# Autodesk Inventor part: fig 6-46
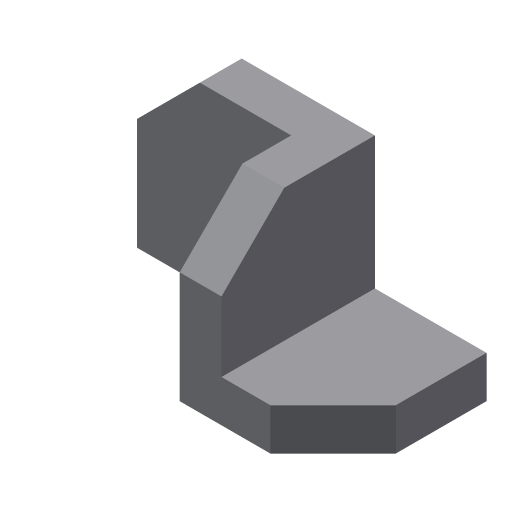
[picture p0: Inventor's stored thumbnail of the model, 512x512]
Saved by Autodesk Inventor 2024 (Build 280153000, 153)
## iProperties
Shininess: 77.0
Angle Display Precision: 2
Document Length Units: 11269
Document Angle Units: 11279
Document Time Units: 11290
Document Mass Units: 11283
Document Length Units Precision: 3
Document Angle Units Precision: 2
Created: 2001-12
Part Number: fig 6-46
Document SubType Name: Modeling
Designer: Renu Muthoo
Density: 1 g/cm^3
Material: Generic
Appearance: Default
Density: 0.0
Volumn: 0.0
Area: 0.0
PropertySet Name: Model Information
Control State: 0
Master: False
Checked Out: False
Author: Renu Muthoo
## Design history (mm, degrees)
sketch "Sketch2"
  geometry: L1 (16.794, 27.142)-(16.794, -22.858); L2 (16.794, -22.858)-(-27.206, -22.858); L3 (-27.206, -22.858)-(-27.206, -10.858); L4 (-27.206, -10.858)-(4.794, -10.858); L5 (4.794, -10.858)-(4.794, 27.142); L6 (4.794, 27.142)-(16.794, 27.142)
  constraints: 12 end point, 4 parallel, 2 perpendicular, 1 vertical
  dimensions: "d0" = 44 distance of L1.end L2.end; "d1" = 50 distance of L1.start L1.end; "d2" = 12 distance of L2.end L3.end
extrude "Extrusion1" new body sketch "Sketch2" distance "d3" = 44; taper "d4" = 0 deg
sketch "Sketch4"
  geometry: L1 (-16.794, -27.142)-(-16.794, 22.858) reference; L2 (27.206, 22.858)-(27.206, 10.858) reference; L3 (-16.794, -27.142)-(-61.001, -27.142); L4 (-61.001, -27.142)-(-61.001, 22.858); L5 (-61.001, 22.858)-(-16.794, 22.858)
  constraints: 6 end point, 2 perpendicular, 1 parallel
extrude "Extrusion3" join sketch "Sketch4" distance "d13" = 12; taper "d14" = 0 deg
chamfer "Chamfer3" distance "d15" = 18; stored, may be unused: second distance "d16" = 2, angle "d17" = 45 deg
body "Solid1"
node "Sketch1"
